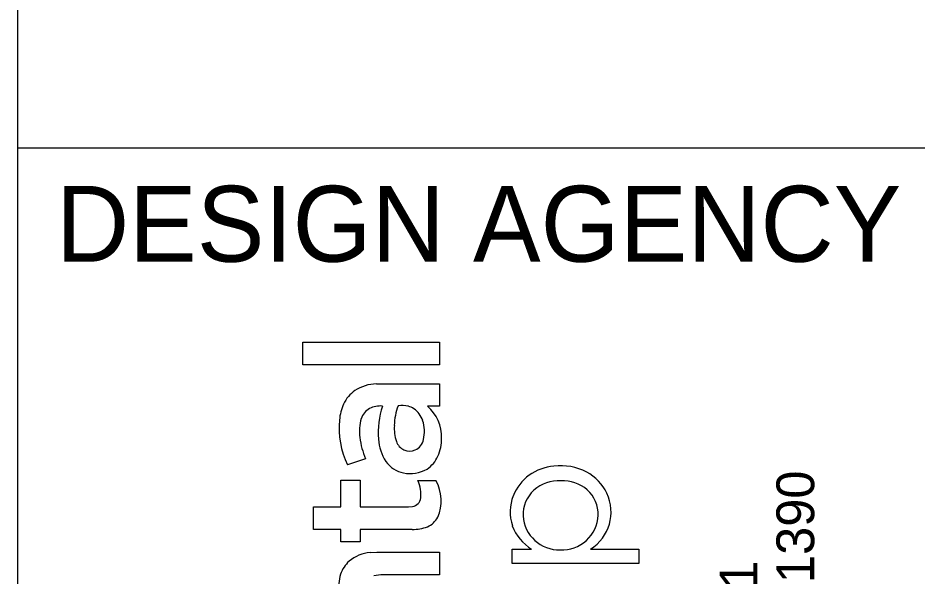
# Model space of a CAD drawing. Extents: x -0.4 to 34, y 0 to 22.
# Drawn here: x 32 to 33.185, y 3.936 to 4.671 of the extents above; entities that cross this region are included whole.
import ezdxf

# ---------------------------------------------------------------- set-up
doc = ezdxf.new("R2010")
doc.units = 0
doc.layers.add('DR_P_Erosion_Control', color=7, linetype='Continuous')
doc.layers.add('GK_Drainage_Nodes', color=7, linetype='Continuous')

msp = doc.modelspace()

# ---------------------------------------------------------------- linework, layer by layer
at = {"layer": 'DR_P_Erosion_Control'}
for p, q in [((32, 0.5), (32, 21.5)), ((32, 4.5), (33.5, 4.5))]:
    msp.add_line(p, q, dxfattribs=at)
at = {"layer": 'GK_Drainage_Nodes'}
for p, q in [((32.3756, 4.2141), (32.3756, 4.244)), ((32.3756, 4.244), (32.5557, 4.244)), ((32.5557, 4.244), (32.5557, 4.2141)), ((32.5557, 4.2141), (32.3756, 4.2141)), ((32.4727, 4.189), (32.5555, 4.1892)), ((32.5555, 4.1892), (32.5557, 4.1596)), ((32.5557, 4.1596), (32.5397, 4.1596)), ((32.4582, 4.0904), (32.4343, 4.0823)), ((32.4254, 4.027), (32.4255, 4.0621)), ((32.4255, 4.0621), (32.4511, 4.0621)), ((32.4511, 4.0621), (32.4512, 4.027)), ((32.527, 4.0616), (32.5511, 4.0616)), ((32.3896, 3.9972), (32.3896, 4.027)), ((32.3896, 4.027), (32.4254, 4.027)), ((32.4512, 4.027), (32.515, 4.027)), ((32.515, 4.027), (32.52, 4.0275)), ((32.4254, 3.9972), (32.3896, 3.9972)), ((32.4254, 3.9807), (32.4254, 3.9972)), ((32.5197, 3.9972), (32.4511, 3.9972)), ((32.4511, 3.9972), (32.4511, 3.9807)), ((32.4511, 3.9807), (32.4254, 3.9807)), ((32.6515, 3.9521), (32.6515, 3.9711)), ((32.6515, 3.9711), (32.6771, 3.9711)), ((32.7549, 3.9713), (32.8186, 3.9711)), ((32.8186, 3.9711), (32.8184, 3.9521)), ((32.4644, 3.9669), (32.4729, 3.9673)), ((32.4729, 3.9673), (32.5557, 3.9673)), ((32.5557, 3.9673), (32.5557, 3.9375)), ((32.8184, 3.9521), (32.6515, 3.9521)), ((32.5557, 3.9375), (32.4814, 3.9375))]:
    msp.add_line(p, q, dxfattribs=at)
msp.add_lwpolyline([(32.3756, 4.2141), (32.3756, 4.244), (32.5557, 4.244), (32.5557, 4.2141)], close=True, dxfattribs=at)
for points in [[(32.4727, 4.189), (32.5555, 4.1892), (32.5557, 4.1596)], [(32.5557, 4.1596), (32.5397, 4.1596)], [(32.4582, 4.0904), (32.4343, 4.0823)], [(32.5197, 3.9972), (32.4511, 3.9972), (32.4511, 3.9807), (32.4254, 3.9807), (32.4254, 3.9972), (32.3896, 3.9972), (32.3896, 4.027), (32.4254, 4.027), (32.4255, 4.0621), (32.4511, 4.0621), (32.4512, 4.027), (32.515, 4.027), (32.52, 4.0275)], [(32.527, 4.0616), (32.5511, 4.0616)], [(32.7549, 3.9713), (32.8186, 3.9711), (32.8184, 3.9521), (32.6515, 3.9521)], [(32.6515, 3.9521), (32.6515, 3.9711), (32.6771, 3.9711)], [(32.4644, 3.9669), (32.4729, 3.9673), (32.5557, 3.9673), (32.5557, 3.9375), (32.4814, 3.9375)]]:
    msp.add_lwpolyline(points, dxfattribs=at)
for centre, radius, start, end in [((32.4745, 4.1326), 0.0565, 91.8942, 122.6317), ((32.4745, 4.1326), 0.0565, 91.8942, 122.6317), ((32.4685, 4.1447), 0.043, 124.537, 155.6594), ((32.4685, 4.1447), 0.043, 124.537, 155.6594), ((32.4882, 4.1361), 0.0646, 155.9764, 175.3149), ((32.4882, 4.1361), 0.0646, 155.9764, 175.3149), ((32.5801, 4.1313), 0.0841, 159.8366, 178.0362), ((32.5801, 4.1313), 0.0841, 159.8366, 178.0362), ((32.5051, 4.1074), 0.053, 79.6696, 94.2322), ((32.5051, 4.1074), 0.053, 79.6696, 94.2322), ((32.4753, 4.1356), 0.024, 119.4252, 161.6629), ((32.4753, 4.1356), 0.024, 119.4252, 161.6629), ((32.4779, 4.1278), 0.0321, 85.3802, 116.6222), ((32.4779, 4.1278), 0.0321, 85.3802, 116.6222), ((32.5879, 4.1251), 0.1129, 162.0821, 184.5285), ((32.5879, 4.1251), 0.1129, 162.0821, 184.5285), ((32.5089, 4.1364), 0.0238, 56.8913, 76.2149), ((32.5089, 4.1364), 0.0238, 56.8913, 76.2149), ((32.5052, 4.1318), 0.0297, 17.5984, 55.7282), ((32.5052, 4.1318), 0.0297, 17.5984, 55.7282), ((32.5055, 4.1191), 0.0529, 358.0746, 49.762), ((32.5055, 4.1191), 0.0529, 358.0746, 49.762), ((32.5364, 4.1308), 0.113, 174.6101, 205.3899), ((32.5364, 4.1308), 0.113, 174.6101, 205.3899), ((32.5076, 4.1265), 0.0576, 163.1369, 188.1675), ((32.5076, 4.1265), 0.0576, 163.1369, 188.1675), ((32.4916, 4.1264), 0.0443, 345.9408, 18.9919), ((32.4916, 4.1264), 0.0443, 345.9408, 18.9919), ((32.5466, 4.1303), 0.0506, 175.5903, 199.8857), ((32.5466, 4.1303), 0.0506, 175.5903, 199.8857), ((32.5473, 4.1297), 0.0973, 186.7598, 203.7981), ((32.5473, 4.1297), 0.0973, 186.7598, 203.7981), ((32.5328, 4.1187), 0.0575, 182.5676, 213.7144), ((32.5328, 4.1187), 0.0575, 182.5676, 213.7144), ((32.5164, 4.1189), 0.0184, 198.2844, 293.3081), ((32.5164, 4.1189), 0.0184, 198.2844, 293.3081), ((32.5152, 4.1199), 0.0199, 295.2883, 347.4639), ((32.5152, 4.1199), 0.0199, 295.2883, 347.4639), ((32.5019, 4.1168), 0.0566, 336.016, 0.5951), ((32.5019, 4.1168), 0.0566, 336.016, 0.5951), ((32.5175, 4.1097), 0.0394, 303.4436, 336.18), ((32.5175, 4.1097), 0.0394, 303.4436, 336.18), ((32.5149, 4.1078), 0.0366, 215.0668, 259.8133), ((32.5149, 4.1078), 0.0366, 215.0668, 259.8133), ((32.7108, 4.0182), 0.0624, 93.9866, 158.3119), ((32.7108, 4.0182), 0.0624, 93.9866, 158.3119), ((32.7156, 4.0065), 0.0746, 62.6889, 97.0135), ((32.7156, 4.0065), 0.0746, 62.6889, 97.0135), ((32.5175, 4.1131), 0.0423, 257.5256, 300.882), ((32.5175, 4.1131), 0.0423, 257.5256, 300.882), ((32.7212, 4.0191), 0.0608, 25.0657, 61.9602), ((32.7212, 4.0191), 0.0608, 25.0657, 61.9602), ((32.4863, 4.042), 0.0452, 10.1545, 25.723), ((32.4863, 4.042), 0.0452, 10.1545, 25.723), ((32.503, 4.0351), 0.0549, 336.589, 28.8991), ((32.503, 4.0351), 0.0549, 336.589, 28.8991), ((32.7138, 4.0102), 0.0513, 87.8965, 131.1812), ((32.7138, 4.0102), 0.0513, 87.8965, 131.1812), ((32.7175, 4.0102), 0.0513, 49.9089, 92.0363), ((32.7175, 4.0102), 0.0513, 49.9089, 92.0363), ((32.4957, 4.0436), 0.0356, 351.914, 10.2059), ((32.4957, 4.0436), 0.0356, 351.914, 10.2059), ((32.7092, 4.0167), 0.0434, 132.3289, 182.0949), ((32.7092, 4.0167), 0.0434, 132.3289, 182.0949), ((32.7215, 4.0173), 0.0433, 358.0487, 47.9447), ((32.7215, 4.0173), 0.0433, 358.0487, 47.9447), ((32.7245, 4.02), 0.0574, 301.9776, 25.6418), ((32.7245, 4.02), 0.0574, 301.9776, 25.6418), ((32.5184, 4.04), 0.0126, 277.6142, 353.7918), ((32.5184, 4.04), 0.0126, 277.6142, 353.7918), ((32.707, 4.0202), 0.0581, 158.656, 198.171), ((32.707, 4.0202), 0.0581, 158.656, 198.171), ((32.5291, 4.0261), 0.0275, 292.6889, 332.0598), ((32.5291, 4.0261), 0.0275, 292.6889, 332.0598), ((32.7135, 4.0181), 0.0478, 183.5974, 271.7045), ((32.7135, 4.0181), 0.0478, 183.5974, 271.7045), ((32.7172, 4.018), 0.0477, 267.3149, 357.4019), ((32.7172, 4.018), 0.0477, 267.3149, 357.4019), ((32.5209, 4.0486), 0.0514, 268.6727, 291.5235), ((32.5209, 4.0486), 0.0514, 268.6727, 291.5235), ((32.7103, 4.0243), 0.0627, 200.8399, 238.0162), ((32.7103, 4.0243), 0.0627, 200.8399, 238.0162), ((32.4687, 3.9172), 0.0499, 94.9706, 130.2248), ((32.4687, 3.9172), 0.0499, 94.9706, 130.2248), ((32.4635, 3.9255), 0.0402, 132.2238, 161.6823), ((32.4635, 3.9255), 0.0402, 132.2238, 161.6823), ((32.4787, 3.9211), 0.056, 162.274, 187.7917), ((32.4787, 3.9211), 0.056, 162.274, 187.7917), ((32.4811, 3.8915), 0.046, 89.6051, 105.3303), ((32.4811, 3.8915), 0.046, 89.6051, 105.3303)]:
    msp.add_arc(centre, radius, start, end, dxfattribs=at)

# ---------------------------------------------------------------- texts
msp.add_text('DESIGN AGENCY', height=0.1, dxfattribs=at).set_placement((32.05, 4.35))
for s, p in [('800.835.1390', (33.0497, 3.6671)), ('450 GRANT ST., AKRON, OH  44311', (32.9749, 2.8374))]:
    msp.add_text(s, height=0.049846, rotation=90, dxfattribs=at).set_placement(p)

doc.saveas('drawing.dxf')
